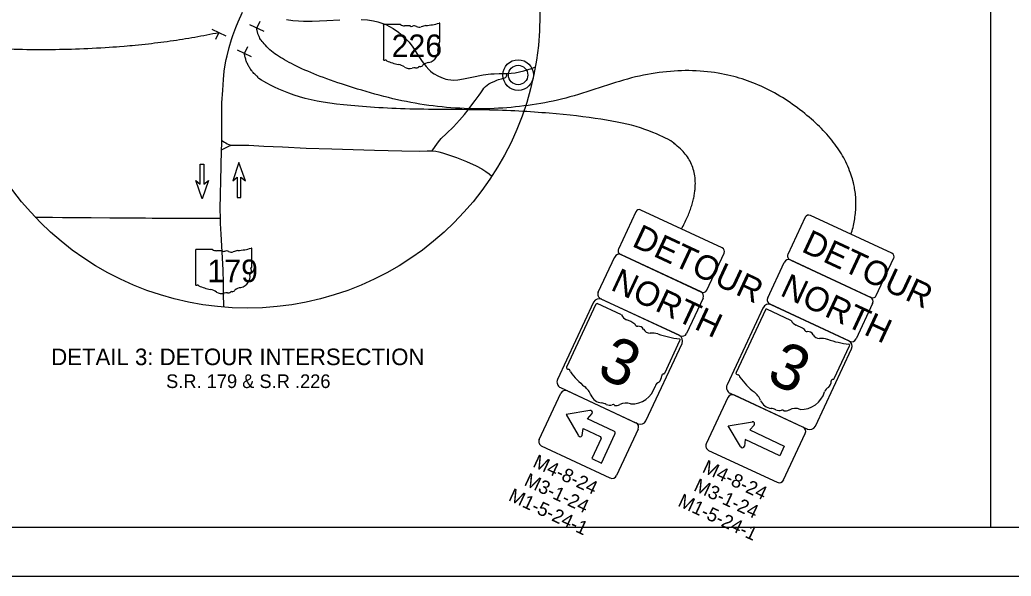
# Model space of a CAD drawing. Extents: x -15.3 to 34, y 0 to 22.
# Drawn here: x 6.79 to 16.96, y 0 to 5.71 of the extents above; entities that cross this region are included whole.
import ezdxf

# ---------------------------------------------------------------- set-up
doc = ezdxf.new("R2010")
doc.units = 0
for name, color, linetype in [('GM_X_County_Road', 7, 'Continuous'), ('GM_X_State_Route', 7, 'Continuous'), ('GM_X_State_Shield', 7, 'Continuous'), ('GM_X_Township_Road', 7, 'Continuous'), ('GM_X_Unincorporated', 7, 'Continuous'), ('PM_P_Cells', 7, 'Continuous'), ('SC_Scratch1', 7, 'Continuous'), ('SH_Border', 7, 'Continuous'), ('SH_Cut_Line', 7, 'Continuous'), ('SH_Text', 7, 'Continuous'), ('SN_P_Signs', 7, 'Continuous')]:
    doc.layers.add(name, color=color, linetype=linetype)

msp = doc.modelspace()

# ---------------------------------------------------------------- linework, layer by layer
at = {"layer": 'GM_X_County_Road'}
for points in [[(11.482, 4.906), (11.503, 4.936), (11.519, 4.959), (11.539, 4.988), (11.552, 5.006), (11.567, 5.023), (11.584, 5.038), (11.602, 5.051), (11.622, 5.062), (11.663, 5.079), (11.683, 5.087), (11.701, 5.094), (11.731, 5.102), (11.766, 5.113), (11.774, 5.117), (11.78, 5.123), (11.784, 5.131), (11.785, 5.141), (11.786, 5.156)], [(11.022, 4.364), (11.053, 4.408), (11.084, 4.455), (11.112, 4.489), (11.168, 4.542), (11.238, 4.61), (11.3, 4.678), (11.352, 4.736), (11.391, 4.785), (11.438, 4.848), (11.463, 4.881), (11.482, 4.906)], [(8.86, 4.373), (8.889, 4.388), (8.915, 4.402), (8.936, 4.411), (8.953, 4.417), (8.97, 4.42)], [(8.863, 4.468), (8.891, 4.452), (8.905, 4.444), (8.919, 4.436), (8.937, 4.43), (8.949, 4.426), (8.97, 4.42)], [(8.97, 4.42), (9.04, 4.422), (9.142, 4.42), (9.293, 4.413), (9.487, 4.403), (9.727, 4.392), (9.991, 4.384), (10.428, 4.37), (10.711, 4.363), (10.886, 4.361), (10.968, 4.364), (11.022, 4.364)], [(11.022, 4.364), (11.057, 4.36), (11.088, 4.353), (11.126, 4.343), (11.189, 4.324), (11.271, 4.295), (11.373, 4.253), (11.473, 4.208), (11.531, 4.178), (11.572, 4.153)], [(11.572, 4.153), (11.604, 4.128), (11.632, 4.103)]]:
    msp.add_lwpolyline(points, dxfattribs=at)
at = {"layer": 'GM_X_State_Route'}
for points in [[(8.884, 2.76), (8.881, 2.906), (8.879, 3.006), (8.876, 3.144), (8.857, 3.509), (8.85, 3.618), (8.85, 3.671), (8.848, 3.769), (8.856, 4.205), (8.86, 4.373), (8.862, 4.433), (8.863, 4.468), (8.863, 4.541), (8.862, 4.636), (8.863, 4.746), (8.865, 4.856), (8.873, 4.986), (8.88, 5.096), (8.889, 5.182), (8.899, 5.245), (8.905, 5.284), (8.909, 5.301), (8.917, 5.338), (8.938, 5.422), (8.963, 5.505), (8.977, 5.546), (9.007, 5.628), (9.031, 5.688), (9.075, 5.787)], [(9.528, 5.712), (9.591, 5.701), (9.65, 5.696), (9.701, 5.694), (9.789, 5.695), (9.942, 5.702), (10.073, 5.707)], [(10.293, 5.711), (10.356, 5.706), (10.42, 5.697), (10.463, 5.687), (10.504, 5.674), (10.544, 5.659), (10.583, 5.64), (10.62, 5.617), (10.674, 5.581), (10.724, 5.54), (10.755, 5.51), (10.783, 5.479), (10.823, 5.427), (10.871, 5.352), (10.918, 5.281), (10.958, 5.23), (10.988, 5.199), (11.004, 5.182), (11.025, 5.165), (11.042, 5.154), (11.078, 5.133), (11.115, 5.116), (11.142, 5.107), (11.162, 5.1), (11.182, 5.096), (11.211, 5.091), (11.235, 5.09), (11.283, 5.093), (11.342, 5.102), (11.428, 5.119), (11.545, 5.142), (11.621, 5.152), (11.655, 5.153), (11.707, 5.156), (11.786, 5.156), (11.832, 5.161), (11.87, 5.165), (11.916, 5.174), (11.96, 5.185), (12.039, 5.209), (12.079, 5.224)]]:
    msp.add_lwpolyline(points, dxfattribs=at)
at = {"layer": 'GM_X_State_Shield'}
for p, q in [((10.52, 5.652), (10.52, 5.3)), ((10.695, 5.658), (10.525, 5.658)), ((11.1, 5.483), (11.1, 5.667)), ((11.1, 5.483), (11.1, 5.483)), ((9.172, 3.174), (9.172, 3.358)), ((8.592, 3.344), (8.592, 2.991)), ((8.768, 3.35), (8.598, 3.35)), ((9.172, 3.174), (9.172, 3.174))]:
    msp.add_line(p, q, dxfattribs=at)
for centre, major_axis, start_param, end_param in [((10.526, 5.653), (0.00672, 0), 1.712693, 3.28349), ((10.736, 5.699), (0.0652, 0), 4.042523, 4.731795), ((10.757, 5.46), (0.234, 0), 1.404758, 1.657858), ((10.81, 5.655), (0.0188, 0), 3.836095, 5.185415), ((10.838, 5.614), (0.0391, 0), 0.950623, 2.079405), ((10.888, 5.67), (0.047, 0), 4.081561, 5.145723), ((10.972, 5.55), (0.124, 0), 1.699011, 2.107814), ((10.893, 6.138), (0.615, 0), 4.814394, 5.042369), ((11.093, 5.668), (0.00646, 0), 6.141152, 7.989035), ((10.928, 5.382), (0.154, 0), 5.101752, 6.440018), ((11.123, 5.405), (0.0436, 0), 2.387724, 3.262537), ((11.098, 5.469), (0.00999, 0), 1.883978, 3.671073), ((11.035, 5.446), (0.06, 0), 5.934695, 6.695948), ((11.093, 5.482), (0.00691, 0), 5.05454, 6.418171), ((10.526, 5.299), (0.00678, 0), 3.00124, 4.508301), ((10.527, 5.335), (0.0517, 0), 4.665946, 4.897461), ((10.538, 5.279), (0.0187, 0), 0.519207, 1.627899), ((10.773, 5.596), (0.444, 0), 4.195997, 4.488961), ((10.641, 5.142), (0.139, 0), 0.823519, 1.323587), ((10.791, 5.278), (0.0882, 0), 4.026481, 4.996735), ((10.842, 5.156), (0.0725, 0), 1.495662, 1.94098), ((10.849, 5.251), (0.047, 0), 4.691044, 5.507374), ((10.891, 5.217), (0.0132, 0), 1.147584, 2.315152), ((10.886, 5.266), (0.0497, 0), 4.937069, 5.64225), ((10.992, 5.201), (0.0843, 0), 1.647645, 2.488434), ((8.966, 3.83), (0.615, 0), 4.814394, 5.042369), ((9.166, 3.359), (0.00646, 0), 6.141152, 7.989035), ((8.599, 3.344), (0.00672, 0), 1.712693, 3.28349), ((8.808, 3.391), (0.0652, 0), 4.042523, 4.731795), ((8.83, 3.152), (0.234, 0), 1.404758, 1.657858), ((8.883, 3.346), (0.0188, 0), 3.836095, 5.185415), ((8.911, 3.305), (0.0391, 0), 0.950623, 2.079405), ((8.961, 3.361), (0.047, 0), 4.081561, 5.145723), ((9.044, 3.242), (0.124, 0), 1.699011, 2.107814), ((9.171, 3.161), (0.00999, 0), 1.883978, 3.671073), ((9.107, 3.137), (0.06, 0), 5.934695, 6.695948), ((9.165, 3.173), (0.00691, 0), 5.05454, 6.418171), ((9, 3.074), (0.154, 0), 5.101752, 6.440018), ((9.195, 3.097), (0.0436, 0), 2.387724, 3.262537), ((8.599, 2.991), (0.00678, 0), 3.00124, 4.508301), ((8.6, 3.027), (0.0517, 0), 4.665946, 4.897461), ((8.611, 2.971), (0.0187, 0), 0.519207, 1.627899), ((8.846, 3.288), (0.444, 0), 4.195997, 4.488961), ((9.065, 2.892), (0.0843, 0), 1.647645, 2.488434), ((8.714, 2.833), (0.139, 0), 0.823519, 1.323587), ((8.864, 2.969), (0.0882, 0), 4.026481, 4.996735), ((8.915, 2.848), (0.0725, 0), 1.495662, 1.94098), ((8.921, 2.943), (0.047, 0), 4.691044, 5.507374), ((8.964, 2.909), (0.0132, 0), 1.147584, 2.315152), ((8.958, 2.957), (0.0497, 0), 4.937069, 5.64225)]:
    msp.add_ellipse(centre, major_axis=major_axis, ratio=0.8, start_param=start_param, end_param=end_param, dxfattribs=at)
at = {"layer": 'GM_X_Township_Road'}
msp.add_lwpolyline([(6.95, 3.684), (7.003, 3.683), (7.127, 3.682), (7.229, 3.681), (7.36, 3.68), (7.523, 3.679), (7.715, 3.677), (7.896, 3.676), (8.015, 3.675), (8.081, 3.675), (8.15, 3.674), (8.247, 3.674), (8.334, 3.673), (8.424, 3.673), (8.506, 3.672), (8.585, 3.672), (8.654, 3.672), (8.71, 3.671), (8.768, 3.671), (8.815, 3.671), (8.85, 3.671)], dxfattribs=at)
at = {"layer": 'GM_X_Unincorporated'}
for radius in [0.157, 0.0996]:
    msp.add_circle((11.902, 5.141), radius, dxfattribs=at)
at = {"layer": 'PM_P_Cells'}
for p, q in [((8.642, 4.022), (8.642, 4.228)), ((8.642, 4.228), (8.679, 4.228)), ((8.66, 4.228), (8.66, 4.228)), ((8.679, 4.228), (8.68, 4.022)), ((9.039, 4.243), (8.975, 4.055)), ((9.039, 4.243), (9.039, 4.243)), ((9.105, 4.055), (9.039, 4.243)), ((8.975, 4.055), (9.021, 4.092)), ((9.021, 4.092), (9.022, 3.886)), ((9.06, 3.886), (9.059, 4.093)), ((9.059, 4.093), (9.105, 4.055)), ((8.662, 3.872), (8.596, 4.059)), ((8.596, 4.059), (8.642, 4.022)), ((8.726, 4.06), (8.662, 3.872)), ((8.68, 4.022), (8.726, 4.06)), ((8.662, 3.872), (8.662, 3.872)), ((9.022, 3.886), (9.06, 3.886)), ((9.041, 3.886), (9.041, 3.886))]:
    msp.add_line(p, q, dxfattribs=at)
at = {"layer": 'SH_Border'}
msp.add_lwpolyline([(1.5, 21.5), (33.5, 21.5), (33.5, 0.5), (1.5, 0.5)], close=True, dxfattribs=at)
at = {"layer": 'SH_Cut_Line'}
msp.add_lwpolyline([(0, 0), (34, 0), (34, 22), (0, 22)], close=True, dxfattribs=at)
at = {"layer": 'SH_Text'}
msp.add_line((16.75, 0.5), (16.75, 21.5), dxfattribs=at)
msp.add_circle((9.125, 5.75), 3, dxfattribs=at)
for points in [[(15.317, 3.507), (15.544, 4.25), (13.895, 5.427), (11.629, 4.61), (9.236, 5.281), (9.223, 5.621)], [(4.7, 4.549), (5.199, 5.477), (7.774, 5.356), (8.832, 5.578)], [(13.578, 3.562), (13.936, 4.226), (12.842, 4.79), (9.167, 4.79), (9.096, 5.362)]]:
    msp.add_open_spline(points, degree=2, dxfattribs=at)
at = {"layer": 'SN_P_Signs'}
for p, q in [((9.223, 5.621), (9.257, 5.694)), ((8.76, 5.613), (8.904, 5.543)), ((9.296, 5.587), (9.15, 5.655)), ((8.832, 5.578), (8.797, 5.506)), ((9.169, 5.328), (9.024, 5.396)), ((9.096, 5.362), (9.13, 5.435)), ((12.724, 2.912), (12.893, 3.275)), ((12.959, 3.299), (13.775, 2.919)), ((14.462, 2.857), (14.631, 3.219)), ((14.697, 3.243), (15.513, 2.863)), ((13.799, 2.852), (13.63, 2.49)), ((12.7, 2.789), (12.399, 2.144)), ((12.962, 2.68), (12.713, 2.796)), ((13.564, 2.465), (12.748, 2.846)), ((15.302, 2.41), (14.486, 2.79)), ((15.537, 2.797), (15.368, 2.434)), ((14.438, 2.733), (14.137, 2.088)), ((14.7, 2.624), (14.452, 2.74)), ((13.405, 2.082), (13.562, 2.419)), ((15.143, 2.027), (15.3, 2.364)), ((13.405, 2.082), (13.405, 2.082)), ((15.143, 2.027), (15.143, 2.027)), ((12.118, 1.401), (12.34, 1.877)), ((12.407, 1.901), (13.109, 1.574)), ((14.054, 1.833), (13.832, 1.358)), ((14.823, 1.53), (14.12, 1.858)), ((12.637, 1.698), (12.393, 1.658)), ((12.393, 1.658), (12.519, 1.445)), ((12.615, 1.615), (12.663, 1.67)), ((12.884, 1.489), (12.615, 1.615)), ((14.056, 1.543), (14.304, 1.584)), ((14.182, 1.33), (14.056, 1.543)), ((14.323, 1.549), (14.278, 1.5)), ((14.823, 1.53), (14.823, 1.53)), ((12.558, 1.443), (12.568, 1.516)), ((12.568, 1.516), (12.745, 1.433)), ((12.756, 1.161), (12.895, 1.458)), ((12.884, 1.489), (12.884, 1.489)), ((13.133, 1.507), (12.912, 1.032)), ((14.278, 1.5), (14.632, 1.335)), ((14.625, 0.988), (14.847, 1.464)), ((12.845, 1.007), (12.143, 1.335)), ((12.753, 1.412), (12.657, 1.207)), ((14.231, 1.401), (14.222, 1.334)), ((14.585, 1.236), (14.231, 1.401)), ((14.632, 1.335), (14.585, 1.236)), ((13.856, 1.291), (14.559, 0.964)), ((12.657, 1.207), (12.756, 1.161)), ((12.657, 1.207), (12.756, 1.161))]:
    msp.add_line(p, q, dxfattribs=at)
for points in [[(13.108, 3.737), (12.931, 3.356)], [(13.995, 3.367), (13.161, 3.756)], [(14.846, 3.682), (14.669, 3.301)], [(15.733, 3.312), (14.9, 3.701)], [(12.95, 3.303), (13.784, 2.914)], [(13.837, 2.934), (14.015, 3.314)], [(15.575, 2.878), (15.753, 3.259)], [(14.688, 3.248), (15.522, 2.859)], [(12.676, 2.81), (12.307, 2.017)], [(13.552, 2.471), (12.759, 2.84)], [(14.414, 2.755), (14.045, 1.962)], [(15.291, 2.415), (14.498, 2.785)], [(13.213, 1.595), (13.583, 2.388)], [(14.951, 1.539), (15.321, 2.332)], [(12.337, 1.934), (13.13, 1.564)], [(14.075, 1.879), (14.868, 1.509)]]:
    msp.add_lwpolyline(points, dxfattribs=at)
for centre, radius, start, end in [((13.145, 3.72), 0.04, 65.0058, 155.0058), ((14.883, 3.665), 0.04, 65.0058, 155.0058), ((12.967, 3.339), 0.04, 155.0058, 245.0058), ((13.978, 3.331), 0.04, 335.0058, 65.0058), ((12.938, 3.253), 0.05, 65.0058, 155.0058), ((14.705, 3.284), 0.04, 155.0058, 245.0058), ((15.717, 3.276), 0.04, 335.0058, 65.0058), ((14.676, 3.198), 0.05, 65.0058, 155.0058), ((12.769, 2.891), 0.05, 155.0058, 245.0058), ((13.754, 2.873), 0.05, 335.0058, 65.0058), ((13.801, 2.951), 0.04, 245.0058, 335.0058), ((14.507, 2.836), 0.05, 155.0058, 245.0058), ((15.492, 2.818), 0.05, 335.0058, 65.0058), ((15.539, 2.895), 0.04, 245.0058, 335.0058), ((12.733, 2.784), 0.0625, 65.0058, 155.0058), ((12.71, 2.785), 0.0109, 73.1359, 163.1359), ((14.471, 2.728), 0.0625, 65.0058, 155.0058), ((13.056, 2.727), 0.105, 206.6253, 246.1177), ((14.448, 2.73), 0.0109, 73.1359, 163.1359), ((12.884, 2.275), 0.378, 55.4925, 69.9941), ((13.128, 2.595), 0.0304, 194.7979, 272.1082), ((13.134, 2.501), 0.0632, 29.4725, 94.1469), ((14.795, 2.672), 0.105, 206.6253, 246.1177), ((14.623, 2.22), 0.378, 55.4925, 69.9941), ((13.255, 2.569), 0.076, 208.862, 269.834), ((13.275, 2.294), 0.2, 72.352, 95.7747), ((13.662, 3.424), 0.994, 250.8503, 263.9123), ((13.526, 2.414), 0.0625, 335.0058, 65.0058), ((13.585, 2.511), 0.05, 245.0058, 335.0058), ((14.866, 2.539), 0.0304, 194.7979, 272.1082), ((14.872, 2.446), 0.0632, 29.4725, 94.1469), ((14.993, 2.514), 0.076, 208.862, 269.834), ((13.553, 2.425), 0.0104, 326.8679, 72.7438), ((15.013, 2.239), 0.2, 72.352, 95.7747), ((15.4, 3.369), 0.994, 250.8503, 263.9123), ((15.264, 2.359), 0.0625, 335.0058, 65.0058), ((15.292, 2.37), 0.0104, 326.8679, 72.7438), ((15.323, 2.455), 0.05, 245.0058, 335.0058), ((12.408, 2.138), 0.011, 146.9642, 233.3124), ((12.441, 2.203), 0.0836, 242.3448, 255.6097), ((12.409, 2.094), 0.0302, 4.7542, 68.2776), ((13.024, 2.512), 0.718, 215.4187, 232.2043), ((13.278, 2.059), 0.097, 315.0388, 358.6554), ((13.391, 2.058), 0.0162, 82.9498, 185.3428), ((13.394, 2.086), 0.0112, 264.6096, 342.7399), ((14.147, 2.082), 0.011, 146.9642, 233.3124), ((14.179, 2.148), 0.0836, 242.3448, 255.6097), ((14.147, 2.039), 0.0302, 4.7542, 68.2776), ((14.762, 2.457), 0.718, 215.4187, 232.2043), ((12.363, 1.991), 0.0625, 155.0058, 245.0058), ((12.442, 1.771), 0.225, 22.19, 50.8418), ((13.067, 2.016), 0.249, 267.3147, 343.9916), ((13.373, 1.925), 0.0705, 111.8123, 161.9354), ((14.101, 1.935), 0.0625, 155.0058, 245.0058), ((15.111, 1.87), 0.0705, 111.8123, 161.9354), ((15.016, 2.004), 0.097, 315.0388, 358.6554), ((15.129, 2.003), 0.0162, 82.9498, 185.3428), ((15.132, 2.03), 0.0112, 264.6096, 342.7399), ((12.386, 1.856), 0.05, 65.0058, 155.0058), ((12.778, 1.918), 0.143, 205.7062, 261.2976), ((14.099, 1.812), 0.05, 65.0058, 155.0058), ((14.18, 1.716), 0.225, 22.19, 50.8418), ((14.805, 1.96), 0.249, 267.3147, 343.9916), ((12.749, 1.66), 0.117, 60.7009, 86.2158), ((12.84, 1.83), 0.0759, 243.7828, 290.5551), ((12.873, 1.739), 0.0214, 40.7575, 107.6542), ((12.906, 1.831), 0.0803, 257.879, 298.2829), ((13.007, 1.64), 0.136, 69.4089, 117.5826), ((14.517, 1.862), 0.143, 205.7062, 261.2976), ((12.644, 1.679), 0.0209, 335.0075, 110.0057), ((14.487, 1.605), 0.117, 60.7009, 86.2158), ((14.578, 1.775), 0.0759, 243.7828, 290.5551), ((14.611, 1.683), 0.0214, 40.7575, 107.6542), ((14.644, 1.776), 0.0803, 257.879, 298.2829), ((14.746, 1.584), 0.136, 69.4089, 117.5826), ((13.088, 1.529), 0.05, 335.0058, 65.0058), ((13.156, 1.621), 0.0625, 245.0058, 335.0058), ((14.307, 1.563), 0.0209, 317.8012, 99.5946), ((14.802, 1.485), 0.05, 335.0058, 65.0058), ((14.894, 1.566), 0.0625, 245.0058, 335.0058), ((12.539, 1.452), 0.0209, 200.0059, 335.0075), ((12.739, 1.419), 0.0156, 335.0058, 65.0058), ((12.874, 1.468), 0.0234, 335.0058, 65.0058), ((12.164, 1.38), 0.05, 155.0058, 245.0058), ((13.877, 1.336), 0.05, 155.0058, 245.0058), ((14.202, 1.337), 0.0209, 199.9963, 352.2104), ((12.866, 1.053), 0.05, 245.0058, 335.0058), ((14.58, 1.009), 0.05, 245.0058, 335.0058)]:
    msp.add_arc(centre, radius, start, end, dxfattribs=at)

# ---------------------------------------------------------------- texts
at = {"layer": 'GM_X_State_Shield'}
for s, p in [('226', (10.605, 5.325)), ('179', (8.716, 3.016))]:
    msp.add_text(s, height=0.232, dxfattribs=at).set_placement(p)
at = {"layer": 'SC_Scratch1'}
for s, p in [('M4-8-24', (12.043, 1.127)), ('M4-8-24', (13.781, 1.072)), ('M3-1-24', (11.954, 0.937)), ('M3-1-24', (13.693, 0.882)), ('M1-5-24-1', (11.793, 0.781)), ('M1-5-24-1', (13.531, 0.725))]:
    msp.add_text(s, height=0.14, rotation=335.0058, dxfattribs=at).set_placement(p)
at = {"layer": 'SH_Text'}
for s, height, p in [('DETAIL 3: DETOUR INTERSECTION', 0.17, (7.114, 2.165)), ('S.R. 179 & S.R .226', 0.14, (8.292, 1.93))]:
    msp.add_text(s, height=height, dxfattribs=at).set_placement(p)
at = {"layer": 'SN_P_Signs'}
for s, height, p in [('DETOUR', 0.25, (13.059, 3.39)), ('DETOUR', 0.25, (14.797, 3.335)), ('NORTH', 0.25, (12.84, 2.941)), ('NORTH', 0.25, (14.578, 2.885)), ('3', 0.469, (12.694, 2.061)), ('3', 0.469, (14.433, 2.006))]:
    msp.add_text(s, height=height, rotation=335.0058, dxfattribs=at).set_placement(p)

doc.saveas('drawing.dxf')
